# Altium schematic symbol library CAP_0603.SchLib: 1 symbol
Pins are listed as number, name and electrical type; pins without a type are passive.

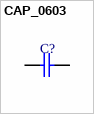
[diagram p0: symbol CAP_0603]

## CAP_0603
designator C?
footprint CAP_0603 (Ceramic chip capacitor)
pins: 1, 2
